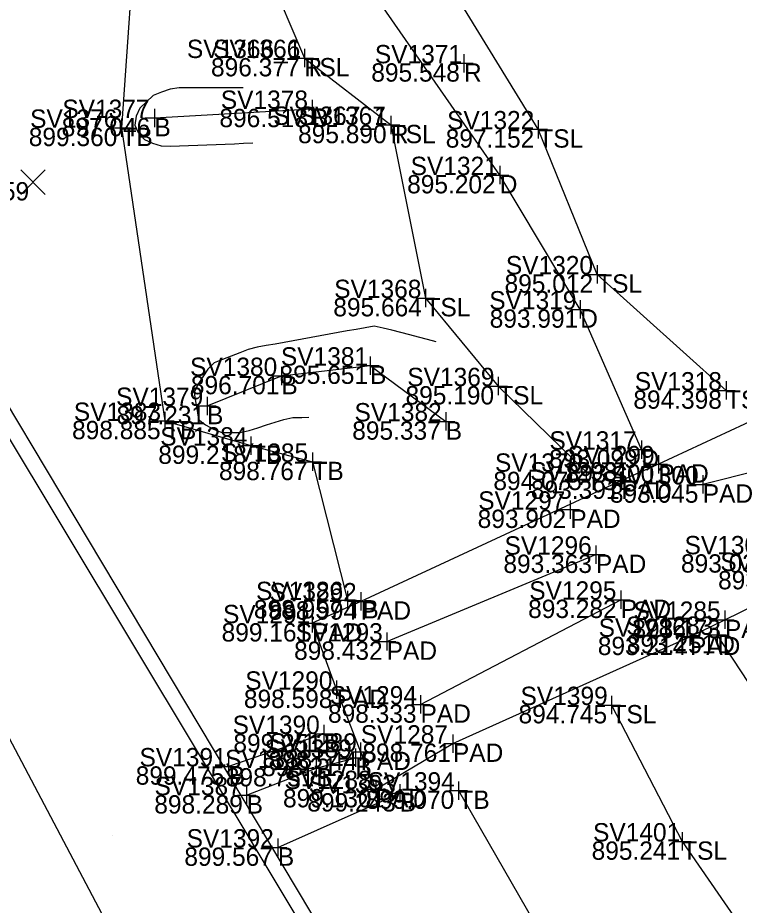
# Model space of a CAD drawing. Extents: x 1918148 to 1919797, y 624701 to 627089.
# Drawn here: x 1918866.27 to 1918905.66, y 625559.4 to 625607.83 of the extents above; entities that cross this region are included whole.
import ezdxf

# ---------------------------------------------------------------- set-up
doc = ezdxf.new("R2010")
doc.units = 0
for name, color, linetype in [('DR_X_Ditch', 7, 'Continuous'), ('DR_X_Erosion_Control', 7, 'Continuous'), ('DT_X_Break_Line', 7, 'Continuous'), ('Ground Shots', 7, 'Continuous'), ('RD_X_Fence', 7, 'Continuous'), ('SV_X_Break_Lines', 7, 'Continuous'), ('SV_X_Random_Point', 7, 'Continuous'), ('SV_X_Shot_Marker', 7, 'Continuous'), ('SV_X_Text_Comment', 7, 'Continuous'), ('SV_X_Text_Elevation', 7, 'Continuous'), ('SV_X_Text_Name', 7, 'Continuous'), ('SV_X_Toe_of_Slope', 7, 'Continuous'), ('SV_X_Top_of_Bank', 7, 'Continuous'), ('UT_X_Gas', 7, 'Continuous'), ('UT_X_Overhead_Combined', 7, 'Continuous')]:
    doc.layers.add(name, color=color, linetype=linetype)

msp = doc.modelspace()

# ---------------------------------------------------------------- linework, layer by layer
at = {"layer": 'DR_X_Ditch'}
for points in [[(1918900.325, 625584.269), (1918896.98, 625591.918), (1918892.588, 625599.25), (1918875.811, 625623.374), (1918874.461, 625624.655), (1918868.906, 625642.744), (1918854.011, 625703.442), (1918836.264, 625761.358)], [(1919022.603, 625413.065), (1918990.744, 625447.13), (1918963.473, 625485.28), (1918945.141, 625512.5), (1918919.457, 625550.942), (1918912.249, 625562.326), (1918904.466, 625574.16)]]:
    msp.add_lwpolyline(points, dxfattribs=at)
at = {"layer": 'DR_X_Erosion_Control'}
msp.add_lwpolyline([(1918914.537, 625579.717), (1918912.802, 625582.939), (1918912.152, 625584.51), (1918910.641, 625587.846), (1918901.249, 625583.469), (1918899.232, 625582.581), (1918884.997, 625575.988), (1918882.345, 625574.796), (1918883.679, 625571.168), (1918884.991, 625567.785), (1918885.817, 625565.746), (1918890.03, 625568.23), (1918902.973, 625574.056), (1918904.88, 625574.98)], close=True, dxfattribs=at)
at = {"layer": 'DT_X_Break_Line'}
for p, q in [((1918912.152, 625584.51), (1918903.671, 625582.37)), ((1918886.416, 625573.797), (1918897.837, 625578.537)), ((1918888.262, 625570.363), (1918899.193, 625576.079))]:
    msp.add_line(p, q, dxfattribs=at)
for points in [[(1918878.583, 625604.012), (1918878.083, 625604.012), (1918877.583, 625604.012), (1918877.083, 625604.012), (1918876.583, 625604.012), (1918876.083, 625604.012), (1918875.583, 625604.012), (1918875.083, 625604.012), (1918874.596, 625603.929), (1918874.123, 625603.768), (1918873.658, 625603.598), (1918873.299, 625603.251), (1918872.937, 625602.902), (1918872.741, 625602.469), (1918872.66, 625601.975), (1918872.853, 625601.564), (1918873.192, 625601.197), (1918873.63, 625600.985), (1918874.107, 625600.836), (1918874.602, 625600.819), (1918875.101, 625600.839), (1918875.601, 625600.86), (1918876.1, 625600.88), (1918876.6, 625600.9), (1918877.1, 625600.921), (1918877.599, 625600.941), (1918878.099, 625600.961), (1918878.598, 625600.982), (1918879.112, 625601.003)], [(1918889.123, 625590.148), (1918888.639, 625590.274), (1918888.155, 625590.4), (1918887.672, 625590.525), (1918887.188, 625590.651), (1918886.704, 625590.777), (1918886.22, 625590.903), (1918885.735, 625591.008), (1918885.243, 625590.919), (1918884.751, 625590.83), (1918884.259, 625590.741), (1918883.767, 625590.652), (1918883.275, 625590.563), (1918882.783, 625590.475), (1918882.291, 625590.386), (1918881.799, 625590.297), (1918881.307, 625590.208), (1918880.815, 625590.119), (1918880.323, 625590.03), (1918879.831, 625589.941), (1918879.339, 625589.852), (1918878.854, 625589.736), (1918878.39, 625589.55), (1918877.926, 625589.365), (1918877.461, 625589.179), (1918876.997, 625588.994), (1918876.658, 625588.654), (1918876.381, 625588.238), (1918876.103, 625587.822), (1918875.906, 625587.389), (1918875.984, 625586.895), (1918876.062, 625586.401), (1918876.14, 625585.907), (1918876.532, 625585.629), (1918876.965, 625585.379), (1918877.417, 625585.199), (1918877.917, 625585.199), (1918878.417, 625585.199), (1918878.9, 625585.303), (1918879.376, 625585.457), (1918879.851, 625585.611), (1918880.327, 625585.766), (1918880.802, 625585.92), (1918881.289, 625586.011), (1918881.789, 625586.027), (1918882.157, 625586.039)]]:
    msp.add_lwpolyline(points, dxfattribs=at)
at = {"layer": 'Ground Shots'}
msp.add_line((1918871.442, 625563.192), (1918871.442, 625563.192), dxfattribs=at)
at = {"layer": 'RD_X_Fence'}
msp.add_lwpolyline([(1918745.788, 625786.434), (1918772.784, 625741.746), (1918796.762, 625701.528), (1918837.417, 625633.441), (1918845.82, 625619.995), (1919000.613, 625360.91)], dxfattribs=at)
at = {"layer": 'SV_X_Break_Lines'}
for points in [[(1918873.736, 625602.365), (1918882.343, 625602.863)], [(1918876.607, 625586.654), (1918880.667, 625588.288), (1918885.505, 625588.854), (1918889.638, 625585.808)], [(1918882.988, 625568.753), (1918877.786, 625566.984)], [(1918878.77, 625565.409), (1918882.574, 625566.889), (1918884.712, 625567.45)], [(1918880.473, 625562.556), (1918887.131, 625565.52)]]:
    msp.add_lwpolyline(points, dxfattribs=at)
at = {"layer": 'SV_X_Random_Point'}
for p, q in [((1918866.438, 625598.196), (1918867.772, 625599.531)), ((1918866.438, 625599.531), (1918867.772, 625598.196))]:
    msp.add_line(p, q, dxfattribs=at)
at = {"layer": 'SV_X_Shot_Marker'}
for p, q in [((1918881.927, 625606.135), (1918881.927, 625605.135)), ((1918881.927, 625606.135), (1918881.927, 625605.135)), ((1918890.635, 625605.848), (1918890.635, 625604.848)), ((1918881.427, 625605.635), (1918882.427, 625605.635)), ((1918881.427, 625605.635), (1918882.427, 625605.635)), ((1918881.927, 625605.635), (1918881.927, 625605.635)), ((1918881.927, 625605.635), (1918881.927, 625605.635)), ((1918890.135, 625605.348), (1918891.135, 625605.348)), ((1918890.635, 625605.348), (1918890.635, 625605.348)), ((1918882.343, 625603.363), (1918882.343, 625602.363)), ((1918873.736, 625602.865), (1918873.736, 625601.865)), ((1918881.843, 625602.863), (1918882.843, 625602.863)), ((1918882.343, 625602.863), (1918882.343, 625602.863)), ((1918871.937, 625602.329), (1918871.937, 625601.329)), ((1918873.236, 625602.365), (1918874.236, 625602.365)), ((1918873.736, 625602.365), (1918873.736, 625602.365)), ((1918886.639, 625602.488), (1918886.639, 625601.488)), ((1918886.639, 625602.488), (1918886.639, 625601.488)), ((1918871.437, 625601.829), (1918872.437, 625601.829)), ((1918871.937, 625601.829), (1918871.937, 625601.829)), ((1918886.139, 625601.988), (1918887.139, 625601.988)), ((1918886.139, 625601.988), (1918887.139, 625601.988)), ((1918886.639, 625601.988), (1918886.639, 625601.988)), ((1918886.639, 625601.988), (1918886.639, 625601.988)), ((1918894.694, 625602.246), (1918894.694, 625601.246)), ((1918894.194, 625601.746), (1918895.194, 625601.746)), ((1918894.694, 625601.746), (1918894.694, 625601.746)), ((1918892.588, 625599.75), (1918892.588, 625598.75)), ((1918892.088, 625599.25), (1918893.088, 625599.25)), ((1918892.588, 625599.25), (1918892.588, 625599.25)), ((1918897.906, 625594.332), (1918897.906, 625593.332)), ((1918897.406, 625593.832), (1918898.406, 625593.832)), ((1918897.906, 625593.832), (1918897.906, 625593.832)), ((1918888.533, 625593.039), (1918888.533, 625592.039)), ((1918888.033, 625592.539), (1918889.033, 625592.539)), ((1918888.533, 625592.539), (1918888.533, 625592.539)), ((1918896.98, 625592.418), (1918896.98, 625591.418)), ((1918896.48, 625591.918), (1918897.48, 625591.918)), ((1918896.98, 625591.918), (1918896.98, 625591.918)), ((1918885.505, 625589.354), (1918885.505, 625588.354)), ((1918880.667, 625588.788), (1918880.667, 625587.788)), ((1918885.005, 625588.854), (1918886.005, 625588.854)), ((1918885.505, 625588.854), (1918885.505, 625588.854)), ((1918880.167, 625588.288), (1918881.167, 625588.288)), ((1918880.667, 625588.288), (1918880.667, 625588.288)), ((1918892.505, 625588.233), (1918892.505, 625587.233)), ((1918904.941, 625587.998), (1918904.941, 625586.998)), ((1918892.005, 625587.733), (1918893.005, 625587.733)), ((1918892.505, 625587.733), (1918892.505, 625587.733)), ((1918904.441, 625587.498), (1918905.441, 625587.498)), ((1918904.941, 625587.498), (1918904.941, 625587.498)), ((1918876.607, 625587.154), (1918876.607, 625586.154)), ((1918874.31, 625586.336), (1918874.31, 625585.336)), ((1918876.107, 625586.654), (1918877.107, 625586.654)), ((1918876.607, 625586.654), (1918876.607, 625586.654)), ((1918889.638, 625586.308), (1918889.638, 625585.308)), ((1918873.81, 625585.836), (1918874.81, 625585.836)), ((1918874.31, 625585.836), (1918874.31, 625585.836)), ((1918889.138, 625585.808), (1918890.138, 625585.808)), ((1918889.638, 625585.808), (1918889.638, 625585.808)), ((1918879.007, 625584.989), (1918879.007, 625583.989)), ((1918878.507, 625584.489), (1918879.507, 625584.489)), ((1918879.007, 625584.489), (1918879.007, 625584.489)), ((1918900.325, 625584.769), (1918900.325, 625583.769)), ((1918882.363, 625584.102), (1918882.363, 625583.102)), ((1918899.825, 625584.269), (1918900.825, 625584.269)), ((1918900.325, 625584.269), (1918900.325, 625584.269)), ((1918901.249, 625583.969), (1918901.249, 625582.969)), ((1918881.863, 625583.602), (1918882.863, 625583.602)), ((1918882.363, 625583.602), (1918882.363, 625583.602)), ((1918897.311, 625583.561), (1918897.311, 625582.561)), ((1918900.749, 625583.469), (1918901.749, 625583.469)), ((1918901.249, 625583.469), (1918901.249, 625583.469)), ((1918896.811, 625583.061), (1918897.811, 625583.061)), ((1918897.311, 625583.061), (1918897.311, 625583.061)), ((1918899.232, 625583.081), (1918899.232, 625582.081)), ((1918898.732, 625582.581), (1918899.732, 625582.581)), ((1918899.232, 625582.581), (1918899.232, 625582.581)), ((1918903.671, 625582.87), (1918903.671, 625581.87)), ((1918903.171, 625582.37), (1918904.171, 625582.37)), ((1918903.671, 625582.37), (1918903.671, 625582.37)), ((1918896.439, 625581.492), (1918896.439, 625580.492)), ((1918895.939, 625580.992), (1918896.939, 625580.992)), ((1918896.439, 625580.992), (1918896.439, 625580.992)), ((1918897.837, 625579.037), (1918897.837, 625578.037)), ((1918897.337, 625578.537), (1918898.337, 625578.537)), ((1918897.837, 625578.537), (1918897.837, 625578.537)), ((1918884.27, 625576.558), (1918884.27, 625575.558)), ((1918884.997, 625576.488), (1918884.997, 625575.488)), ((1918899.193, 625576.579), (1918899.193, 625575.579)), ((1918883.77, 625576.058), (1918884.77, 625576.058)), ((1918884.27, 625576.058), (1918884.27, 625576.058)), ((1918884.497, 625575.988), (1918885.497, 625575.988)), ((1918884.997, 625575.988), (1918884.997, 625575.988)), ((1918898.693, 625576.079), (1918899.693, 625576.079)), ((1918899.193, 625576.079), (1918899.193, 625576.079)), ((1918882.345, 625575.296), (1918882.345, 625574.296)), ((1918904.88, 625575.48), (1918904.88, 625574.48)), ((1918881.845, 625574.796), (1918882.845, 625574.796)), ((1918882.345, 625574.796), (1918882.345, 625574.796)), ((1918904.38, 625574.98), (1918905.38, 625574.98)), ((1918904.88, 625574.98), (1918904.88, 625574.98)), ((1918886.416, 625574.297), (1918886.416, 625573.297)), ((1918902.973, 625574.556), (1918902.973, 625573.556)), ((1918904.466, 625574.66), (1918904.466, 625573.66)), ((1918885.916, 625573.797), (1918886.916, 625573.797)), ((1918886.416, 625573.797), (1918886.416, 625573.797)), ((1918902.473, 625574.056), (1918903.473, 625574.056)), ((1918902.973, 625574.056), (1918902.973, 625574.056)), ((1918903.966, 625574.16), (1918904.966, 625574.16)), ((1918904.466, 625574.16), (1918904.466, 625574.16)), ((1918883.679, 625571.668), (1918883.679, 625570.668)), ((1918883.179, 625571.168), (1918884.179, 625571.168)), ((1918883.679, 625571.168), (1918883.679, 625571.168)), ((1918888.262, 625570.863), (1918888.262, 625569.863)), ((1918898.687, 625570.83), (1918898.687, 625569.83)), ((1918887.762, 625570.363), (1918888.762, 625570.363)), ((1918888.262, 625570.363), (1918888.262, 625570.363)), ((1918898.187, 625570.33), (1918899.187, 625570.33)), ((1918898.687, 625570.33), (1918898.687, 625570.33)), ((1918882.988, 625569.253), (1918882.988, 625568.253)), ((1918882.488, 625568.753), (1918883.488, 625568.753)), ((1918882.988, 625568.753), (1918882.988, 625568.753)), ((1918890.03, 625568.73), (1918890.03, 625567.73)), ((1918884.712, 625567.95), (1918884.712, 625566.95)), ((1918884.991, 625568.285), (1918884.991, 625567.285)), ((1918889.53, 625568.23), (1918890.53, 625568.23)), ((1918890.03, 625568.23), (1918890.03, 625568.23)), ((1918877.786, 625567.484), (1918877.786, 625566.484)), ((1918884.212, 625567.45), (1918885.212, 625567.45)), ((1918884.491, 625567.785), (1918885.491, 625567.785)), ((1918884.712, 625567.45), (1918884.712, 625567.45)), ((1918884.991, 625567.785), (1918884.991, 625567.785)), ((1918877.286, 625566.984), (1918878.286, 625566.984)), ((1918877.786, 625566.984), (1918877.786, 625566.984)), ((1918882.574, 625567.389), (1918882.574, 625566.389)), ((1918882.074, 625566.889), (1918883.074, 625566.889)), ((1918882.574, 625566.889), (1918882.574, 625566.889)), ((1918885.817, 625566.246), (1918885.817, 625565.246)), ((1918887.131, 625566.02), (1918887.131, 625565.02)), ((1918890.33, 625566.165), (1918890.33, 625565.165)), ((1918878.77, 625565.909), (1918878.77, 625564.909)), ((1918885.317, 625565.746), (1918886.317, 625565.746)), ((1918885.817, 625565.746), (1918885.817, 625565.746)), ((1918886.631, 625565.52), (1918887.631, 625565.52)), ((1918887.131, 625565.52), (1918887.131, 625565.52)), ((1918889.83, 625565.665), (1918890.83, 625565.665)), ((1918890.33, 625565.665), (1918890.33, 625565.665)), ((1918878.27, 625565.409), (1918879.27, 625565.409)), ((1918878.77, 625565.409), (1918878.77, 625565.409)), ((1918880.473, 625563.056), (1918880.473, 625562.056)), ((1918902.545, 625563.387), (1918902.545, 625562.387)), ((1918902.045, 625562.887), (1918903.045, 625562.887)), ((1918902.545, 625562.887), (1918902.545, 625562.887)), ((1918879.973, 625562.556), (1918880.973, 625562.556)), ((1918880.473, 625562.556), (1918880.473, 625562.556))]:
    msp.add_line(p, q, dxfattribs=at)
at = {"layer": 'SV_X_Toe_of_Slope'}
for points in [[(1918904.941, 625587.498), (1918897.906, 625593.832), (1918894.694, 625601.746), (1918878.044, 625628.864), (1918871.636, 625644.449), (1918857.157, 625704.2), (1918839.619, 625762.849)], [(1918827.685, 625758.54), (1918846.414, 625704.773), (1918864.058, 625647.197), (1918871.574, 625627.631), (1918873.72, 625621.701), (1918876.275, 625614.72), (1918879.9, 625610.372), (1918881.927, 625605.635), (1918886.639, 625601.988), (1918888.533, 625592.539), (1918892.505, 625587.733), (1918897.311, 625583.061)], [(1918898.687, 625570.33), (1918902.545, 625562.887), (1918917.761, 625540.856), (1918929.731, 625525.322), (1918942.077, 625509.757), (1918961.186, 625481.315), (1918987.058, 625442.578), (1919013.134, 625409.902)]]:
    msp.add_lwpolyline(points, dxfattribs=at)
at = {"layer": 'SV_X_Top_of_Bank'}
for points in [[(1918817.463, 625755.24), (1918837.993, 625713.423), (1918855.659, 625644.061), (1918865.13, 625625.309), (1918872.8, 625614.063), (1918871.937, 625601.829), (1918874.31, 625585.836), (1918879.007, 625584.489), (1918882.363, 625583.602), (1918884.27, 625576.058)], [(1918890.33, 625565.665), (1918904.687, 625540.709), (1918916.608, 625519.356), (1918928.233, 625497.866), (1918947.006, 625474.519), (1918970.062, 625431.738), (1918997.613, 625399.314)]]:
    msp.add_lwpolyline(points, dxfattribs=at)
at = {"layer": 'UT_X_Gas'}
msp.add_lwpolyline([(1918759.168, 625917.084), (1918754.306, 625900.243), (1918749.452, 625846.761), (1918748.461, 625829.004), (1918743.942, 625797.46), (1918743.006, 625773.569), (1918765.829, 625740.859), (1918795.68, 625692.777), (1918822.428, 625647.505), (1918838.928, 625617.602), (1918864.37, 625571.208), (1918888.363, 625525.758), (1918914.136, 625478.379), (1918935.187, 625439.317), (1918956.473, 625399.657), (1918975.299, 625371.47), (1919011.933, 625334.484), (1919018.035, 625313.569)], dxfattribs=at)
at = {"layer": 'UT_X_Overhead_Combined'}
msp.add_lwpolyline([(1918749.028, 625800.122), (1918759.416, 625761.901), (1918898.018, 625531.272), (1919016.404, 625331.435)], dxfattribs=at)

# ---------------------------------------------------------------- texts
at = {"layer": 'SV_X_Text_Comment'}
for s, p in [('TSL', (1918881.927, 625604.635)), ('R', (1918881.927, 625604.635)), ('R', (1918890.635, 625604.348)), ('B', (1918882.343, 625601.863)), ('B', (1918873.736, 625601.365)), ('TB', (1918871.937, 625600.829)), ('TSL', (1918886.639, 625600.988)), ('R', (1918886.639, 625600.988)), ('TSL', (1918894.694, 625600.746)), ('D', (1918892.588, 625598.25)), ('TSL', (1918897.906, 625592.832)), ('TSL', (1918888.533, 625591.539)), ('D', (1918896.98, 625590.918)), ('B', (1918885.505, 625587.854)), ('B', (1918880.667, 625587.288)), ('TSL', (1918892.505, 625586.733)), ('TSL', (1918904.941, 625586.498)), ('B', (1918876.607, 625585.654)), ('TB', (1918874.31, 625584.836)), ('B', (1918889.638, 625584.808)), ('TB', (1918879.007, 625583.489)), ('D', (1918900.325, 625583.269)), ('TB', (1918882.363, 625582.602)), ('PAD', (1918901.249, 625582.469)), ('TSL', (1918897.311, 625582.061)), ('PAD', (1918899.232, 625581.581)), ('PAD', (1918903.671, 625581.37)), ('PAD', (1918896.439, 625579.992)), ('PAD', (1918897.837, 625577.537)), ('TB', (1918884.27, 625575.058)), ('PAD', (1918884.997, 625574.988)), ('PAD', (1918899.193, 625575.079)), ('PAD', (1918882.345, 625573.796)), ('PAD', (1918904.88, 625573.98)), ('PAD', (1918886.416, 625572.797)), ('PAD', (1918902.973, 625573.056)), ('D', (1918904.466, 625573.16)), ('PAD', (1918883.679, 625570.168)), ('PAD', (1918888.262, 625569.363)), ('TSL', (1918898.687, 625569.33)), ('B', (1918882.988, 625567.753)), ('PAD', (1918890.03, 625567.23)), ('B', (1918884.712, 625566.45)), ('PAD', (1918884.991, 625566.785)), ('B', (1918877.786, 625565.984)), ('B', (1918882.574, 625565.889)), ('PAD', (1918885.817, 625564.746)), ('B', (1918887.131, 625564.52)), ('TB', (1918890.33, 625564.665)), ('B', (1918878.77, 625564.409)), ('TSL', (1918902.545, 625561.887)), ('B', (1918880.473, 625561.556))]:
    msp.add_text(s, height=1, dxfattribs=at).set_placement(p)
at = {"layer": 'SV_X_Text_Elevation'}
for s, p in [('896.377', (1918876.824, 625604.635)), ('896.377', (1918876.824, 625604.635)), ('895.548', (1918885.576, 625604.348)), ('896.518', (1918877.284, 625601.863)), ('897.046', (1918868.672, 625601.365)), ('899.360', (1918866.876, 625600.829)), ('895.890', (1918881.578, 625600.988)), ('895.890', (1918881.578, 625600.988)), ('897.152', (1918889.638, 625600.746)), ('899.559', (1918862.064, 625597.864)), ('895.202', (1918887.532, 625598.25)), ('895.012', (1918892.85, 625592.832)), ('895.664', (1918883.502, 625591.539)), ('893.991', (1918892.039, 625590.918)), ('895.651', (1918880.564, 625587.854)), ('896.701', (1918875.726, 625587.288)), ('895.190', (1918887.444, 625586.733)), ('894.398', (1918899.882, 625586.498)), ('897.231', (1918871.666, 625585.654)), ('898.885', (1918869.239, 625584.836)), ('895.337', (1918884.535, 625584.808)), ('899.218', (1918873.948, 625583.489)), ('893.099', (1918895.284, 625583.269)), ('898.767', (1918877.26, 625582.602)), ('893.400', (1918896.188, 625582.469)), ('894.075', (1918892.24, 625582.061)), ('893.391', (1918894.291, 625581.581)), ('893.045', (1918898.6, 625581.37)), ('893.902', (1918891.383, 625579.992)), ('893.363', (1918892.787, 625577.537)), ('893.038', (1918902.482, 625577.556)), ('893.517', (1918904.506, 625576.644)), ('898.957', (1918879.167, 625575.058)), ('898.994', (1918879.966, 625574.988)), ('893.282', (1918894.137, 625575.079)), ('899.161', (1918877.404, 625573.796)), ('893.173', (1918899.83, 625573.98)), ('898.432', (1918881.36, 625572.797)), ('893.214', (1918897.942, 625573.056)), ('893.251', (1918899.525, 625573.16)), ('898.598', (1918878.62, 625570.168)), ('898.333', (1918883.212, 625569.363)), ('894.745', (1918893.616, 625569.33)), ('899.251', (1918878.047, 625567.753)), ('898.761', (1918885.089, 625567.23)), ('898.317', (1918879.609, 625566.45)), ('898.544', (1918879.96, 625566.785)), ('899.475', (1918872.715, 625565.984)), ('898.751', (1918877.633, 625565.889)), ('899.130', (1918880.756, 625564.746)), ('899.243', (1918882.081, 625564.52)), ('899.070', (1918885.269, 625564.665)), ('898.289', (1918873.729, 625564.409)), ('899.567', (1918875.37, 625561.556)), ('895.241', (1918897.604, 625561.887))]:
    msp.add_text(s, height=1, dxfattribs=at).set_placement(p)
at = {"layer": 'SV_X_Text_Name'}
for s, p in [('SV1366_1', (1918875.51, 625605.635)), ('SV1366', (1918876.94, 625605.635)), ('SV1371', (1918885.771, 625605.348)), ('SV1378', (1918877.361, 625602.863)), ('SV1377', (1918868.71, 625602.365)), ('SV1376', (1918866.95, 625601.829)), ('SV1367_1', (1918880.222, 625601.988)), ('SV1367', (1918881.613, 625601.988)), ('SV1322', (1918889.715, 625601.746)), ('SV1321', (1918887.724, 625599.25)), ('SV1320', (1918892.922, 625593.832)), ('SV1368', (1918883.551, 625592.539)), ('SV1319', (1918892.016, 625591.918)), ('SV1381', (1918880.641, 625588.854)), ('SV1380', (1918875.683, 625588.288)), ('SV1369', (1918887.541, 625587.733)), ('SV1318', (1918899.959, 625587.498)), ('SV1379', (1918871.643, 625586.654)), ('SV1383', (1918869.337, 625585.836)), ('SV1382', (1918884.659, 625585.808)), ('SV1384', (1918874.053, 625584.489)), ('SV1317', (1918895.299, 625584.269)), ('SV1385', (1918877.369, 625583.602)), ('SV1299', (1918896.285, 625583.469)), ('SV1370', (1918892.327, 625583.061)), ('SV1298', (1918894.25, 625582.581)), ('SV1300', (1918898.687, 625582.37)), ('SV1297', (1918891.413, 625580.992)), ('SV1296', (1918892.85, 625578.537)), ('SV1301', (1918902.677, 625578.556)), ('SV1282', (1918904.63, 625577.644)), ('SV1295', (1918894.199, 625576.079)), ('SV1386', (1918879.283, 625576.058)), ('SV1292', (1918880.018, 625575.988)), ('SV1291', (1918877.481, 625574.796)), ('SV1285', (1918899.886, 625574.98)), ('SV1283', (1918899.493, 625574.16)), ('SV1293', (1918881.443, 625573.797)), ('SV1286', (1918897.986, 625574.056)), ('SV1290', (1918878.695, 625571.168)), ('SV1294', (1918883.308, 625570.363)), ('SV1399', (1918893.723, 625570.33)), ('SV1390', (1918878.004, 625568.753)), ('SV1287', (1918885.004, 625568.23)), ('SV1389', (1918879.748, 625567.45)), ('SV1289', (1918880.027, 625567.785)), ('SV1391', (1918872.922, 625566.984)), ('SV1388', (1918877.592, 625566.889)), ('SV1288', (1918880.835, 625565.746)), ('SV1393', (1918882.158, 625565.52)), ('SV1394', (1918885.376, 625565.665)), ('SV1387', (1918873.744, 625565.409)), ('SV1392', (1918875.494, 625562.556)), ('SV1401', (1918897.681, 625562.887))]:
    msp.add_text(s, height=1, dxfattribs=at).set_placement(p)

doc.saveas('drawing.dxf')
